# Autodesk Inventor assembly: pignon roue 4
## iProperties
Author: Administrateur
Created: 2001-04
Part Number: pignon roue 4
Document SubType Name: Assemblage
Designer: Administrateur
Control State: 0
Master: False
Checked Out: False
PropertySet Name: Design Tracking Control
Shininess: 60.0
PropertySet Name: _Private Model Information
Length Units: 11269
Angle Units: 11283
Time Units: 11279
Mass Units: 11290
Length Display Precision: 3
Angle Display Precision: 2
Compacted: False
Density: 0.0
Volumn: 0.0
Area: 0.0
PropertySet Name: Model Information
